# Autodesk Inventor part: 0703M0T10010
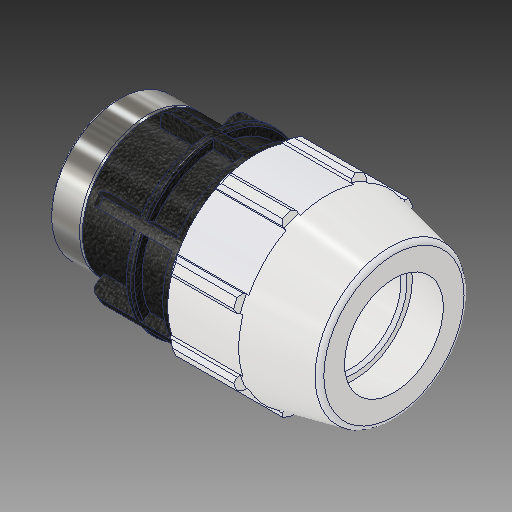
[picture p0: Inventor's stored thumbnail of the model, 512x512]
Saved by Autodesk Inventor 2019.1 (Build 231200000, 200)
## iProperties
Created: 2017-02
Part Number: 0703M0T10010
Material: PVC-Piping
Description: PLASSON FEMALE ADAPTOR G 1'' - 1''F
Document SubType Name: Modeling
Designer: KIM
Mass: 92.6774 g
Surface Area: 199.44 cm^2
Volume: 66.1981 cm^3
Density: 1.4 g/cm^3
Appearance: PTFE
Author: KIM
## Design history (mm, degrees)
derived "0703M0T.ipt"
feature "Solid1::0703M0T.ipt"
tag "TaggingFeature1"
body "Solid1"
other parameters: "d2" = 33.3, "d4" = 13.28057, "d5" = 23.241, "d7" = 64.008, "d9" = 13.28057, "d11" = 2.65611, "d12" = 51.2064, "d13" = 120 deg, "d14" = 49.95, "d15" = 12 deg, "d16" = 57.6072, "d18" = 1.665, "d19" = 35 deg, "d20" = 17.5 deg, "d21" = 59.52744, "d23" = 0, "d25" = 360 deg, "d27" = 1.28016, "d34" = 3.2004, "d35" = 27.8892, "d36" = 0, "d42" = 23.241, "d43" = 1.92024, "d46" = 0.999, "d49" = 67.056, "d51" = 92.964, "d53" = 0.666, "d55" = 360 deg, "d61" = 21.082, "d62" = 31.635, "d63" = 30.291, "d64" = 30.988, "d65" = 3.2004, "d66" = 0.5, "d67" = 1, "d68" = 10.541, "d69" = 46.08576, "d70" = 1.27, "d_" = 33.3, "E_" = 64.008, "H_" = 92.964, "l_" = 67.056, "l_2" = 21.082, "G_" = 30.291
